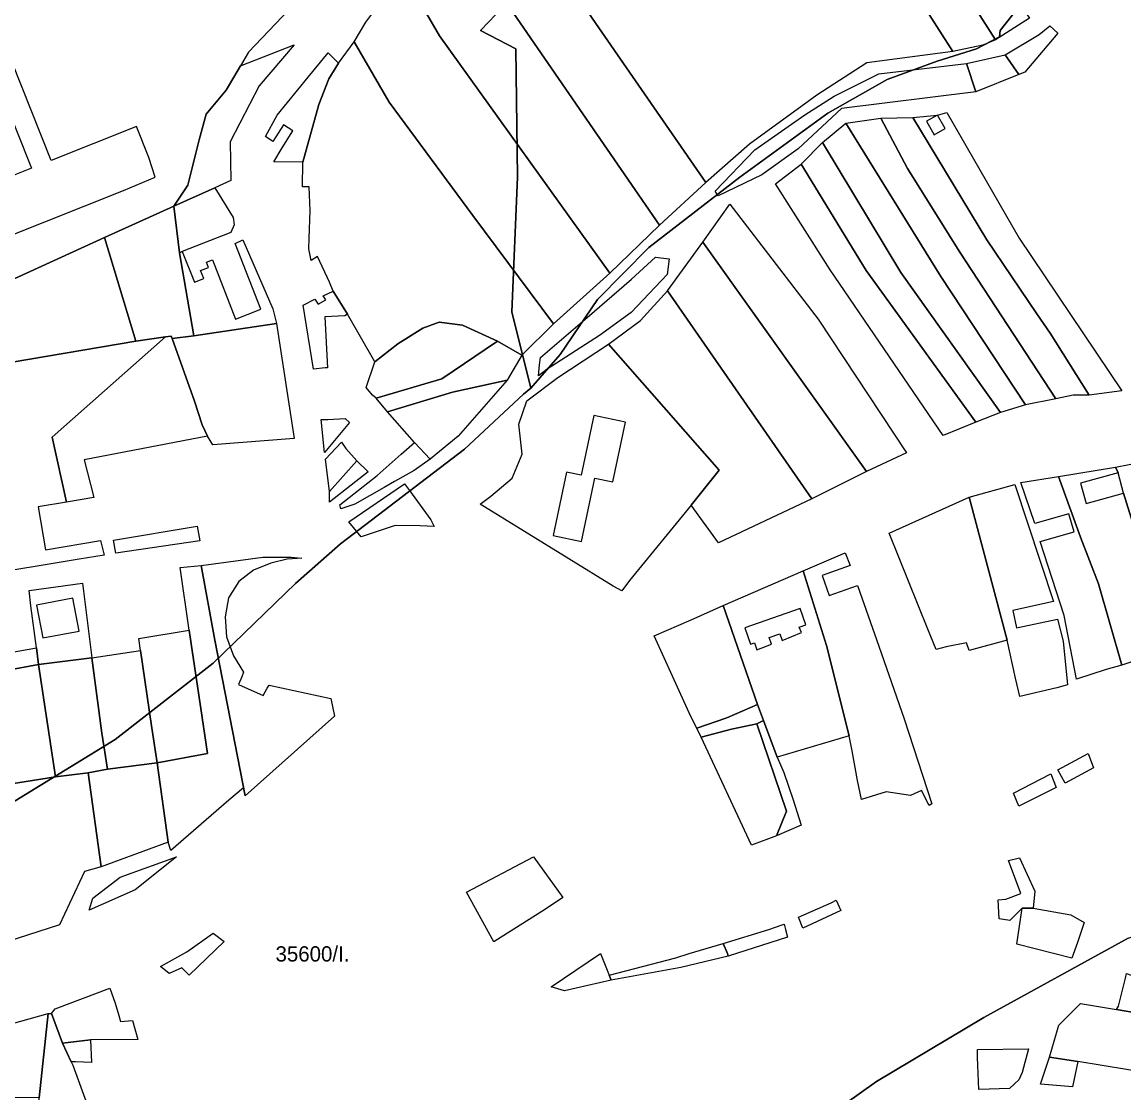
# Model space of a CAD drawing. Extents: x -532083 to -529270, y -1180561 to -1176456.
# Drawn here: x -531139.4 to -530778.9, y -1178347.7 to -1177997.2 of the extents above; entities that cross this region are included whole.
import ezdxf

# ---------------------------------------------------------------- set-up
doc = ezdxf.new("R2010")
doc.units = 0
for name, color, linetype in [('95560013', 7, 'Continuous'), ('95590013', 7, 'Continuous'), ('95610013', 7, 'Continuous'), ('95660013', 7, 'Continuous')]:
    doc.layers.add(name, color=color, linetype=linetype)

msp = doc.modelspace()

# ---------------------------------------------------------------- linework, layer by layer
at = {"layer": '95560013'}
for points in [[(-530820.9913, -1178003.06245), (-530930.6673, -1177831.22145), (-530920.0483, -1177825.55545), (-530869.5383, -1177900.90345), (-530842.0393, -1177949.25845), (-530809.7883, -1177995.91145)], [(-530872.2543, -1177948.23745), (-530914.0103, -1177878.42845), (-530941.5973, -1177837.12545), (-530930.6673, -1177831.22145), (-530820.9913, -1178003.06245), (-530825.0653, -1178004.76545), (-530834.9103, -1178006.80845)], [(-530915.7083, -1178049.71545), (-530951.6933, -1177997.61445), (-530993.4503, -1177936.65945), (-530984.6873, -1177911.73145), (-530959.2033, -1177846.27645), (-530941.5973, -1177837.12545), (-530914.0103, -1177878.42845), (-530872.2543, -1177948.23745), (-530834.9103, -1178006.80845), (-530863.0883, -1178010.55445), (-530879.3833, -1178021.11145), (-530901.4493, -1178037.11645)], [(-530947.0613, -1178079.33945), (-531002.7723, -1178001.74145), (-531014.8703, -1177980.98445), (-531001.4993, -1177960.86645), (-530930.8253, -1178063.69245)], [(-530991.9483, -1178060.49845), (-531019.3263, -1178023.45545), (-531030.7873, -1178003.65745), (-531026.9673, -1177997.27045), (-531014.8703, -1177980.98445), (-531002.7723, -1178001.74145), (-530947.0613, -1178079.33945), (-530965.5253, -1178095.94445)], [(-530800.5353, -1178000.82745), (-530811.3833, -1178013.60045), (-530813.2703, -1178014.31045), (-530817.7503, -1178007.92345), (-530806.6673, -1178001.30045), (-530803.1293, -1177998.46145)], [(-531038.8063, -1178082.35745), (-531042.6983, -1178073.96445), (-531044.8383, -1178075.23345), (-531045.6173, -1178071.42645), (-531045.4223, -1178067.91445), (-531045.1203, -1178058.95245), (-531045.4933, -1178051.07545), (-531047.6113, -1178051.10845), (-531047.5143, -1178043.08645), (-531042.3023, -1178024.23045), (-531039.0233, -1178015.75445), (-531035.8703, -1178010.69345), (-531030.7873, -1178003.65745), (-531019.3263, -1178023.45545), (-530991.9483, -1178060.49845), (-530965.5253, -1178095.94445), (-530975.8543, -1178106.22745), (-530983.8033, -1178101.69345), (-530995.3373, -1178096.37845), (-531002.9743, -1178095.44045), (-531008.2403, -1178097.34545), (-531016.4083, -1178102.46645), (-531023.9643, -1178108.40745), (-531032.8833, -1178092.84045), (-531037.6453, -1178085.27745)], [(-530827.4193, -1178019.98745), (-530871.2943, -1178025.51645), (-530885.4593, -1178038.72045), (-530897.3353, -1178047.18745), (-530911.6433, -1178054.07645), (-530912.6443, -1178052.49845), (-530899.6243, -1178039.00745), (-530883.3133, -1178027.52545), (-530873.7273, -1178021.49845), (-530859.1323, -1178014.17845), (-530830.4853, -1178010.76245)], [(-530813.2703, -1178014.31045), (-530827.4193, -1178019.98745), (-530830.4853, -1178010.76245), (-530817.7503, -1178007.92345)], [(-530838.7863, -1178080.44245), (-530869.8673, -1178030.34345), (-530858.5063, -1178028.62345), (-530849.7183, -1178045.17945), (-530832.5693, -1178072.48645), (-530801.2503, -1178120.46245), (-530811.0813, -1178122.43545)], [(-530832.5693, -1178072.48645), (-530849.7183, -1178045.17945), (-530858.5063, -1178028.62345), (-530847.9393, -1178028.44545), (-530823.7703, -1178068.43845), (-530807.4743, -1178092.74245), (-530803.0933, -1178099.07145), (-530790.2983, -1178119.28945), (-530795.5483, -1178119.27945), (-530801.2503, -1178120.46245)], [(-530790.2983, -1178119.28945), (-530803.0933, -1178099.07145), (-530807.4743, -1178092.74245), (-530823.7703, -1178068.43845), (-530847.9393, -1178028.44545), (-530839.8763, -1178027.64445), (-530843.5293, -1178029.68445), (-530841.0593, -1178034.10845), (-530837.4063, -1178032.06845), (-530839.8763, -1178027.64445), (-530836.8253, -1178026.85245), (-530813.1853, -1178067.90745), (-530779.6063, -1178117.88345)], [(-530851.8613, -1178079.15245), (-530877.5843, -1178036.57945), (-530869.8673, -1178030.34345), (-530838.7863, -1178080.44245), (-530811.0813, -1178122.43545), (-530819.3393, -1178124.99945)], [(-530863.3093, -1178078.50745), (-530884.5303, -1178043.67545), (-530877.5843, -1178036.57945), (-530851.8613, -1178079.15245), (-530819.3393, -1178124.99945), (-530827.4013, -1178128.15445)], [(-530875.0123, -1178078.29245), (-530892.8903, -1178050.12545), (-530884.5303, -1178043.67545), (-530863.3093, -1178078.50745), (-530827.4013, -1178128.15445), (-530838.0183, -1178132.49345)], [(-531090.6953, -1178268.30045), (-531091.5973, -1178265.58545), (-531095.2053, -1178239.64845), (-531078.6683, -1178236.63245), (-531080.4723, -1178224.87045), (-531084.0803, -1178200.74245), (-531084.6823, -1178196.21845), (-531087.6883, -1178175.70945), (-531080.7733, -1178175.10645), (-531076.2633, -1178199.53545), (-531066.3413, -1178250.50545), (-531066.9423, -1178247.79145), (-531071.7193, -1178251.91645)], [(-531116.5533, -1178205.26645), (-531133.9863, -1178207.47245), (-531134.6903, -1178202.00245), (-531136.4593, -1178188.24745), (-531137.0783, -1178183.28645), (-531119.5603, -1178180.83645)], [(-531122.8083, -1178185.77945), (-531134.6053, -1178188.04045), (-531132.5443, -1178198.79045), (-531120.7483, -1178196.52845)], [(-531127.0763, -1178292.72945), (-531147.8233, -1178299.36545), (-531167.3663, -1178304.49245), (-531176.0273, -1178251.70945), (-531165.3103, -1178250.05545), (-531149.8553, -1178247.57545), (-531128.4223, -1178244.26745), (-531117.7563, -1178242.96545), (-531113.5463, -1178273.72945), (-531118.9583, -1178275.23745)], [(-531102.4213, -1178281.26945), (-531117.4553, -1178287.90445), (-531116.2523, -1178283.98345), (-531107.2323, -1178277.04645), (-531088.8913, -1178270.41145)]]:
    msp.add_lwpolyline(points, close=True, dxfattribs=at)
for points in [[(-531155.6903, -1177952.50245), (-531115.2653, -1177942.02045), (-531094.3663, -1177932.91745), (-531032.2163, -1177904.22945), (-530985.0123, -1177891.27045), (-530995.8013, -1177914.67845), (-531001.4993, -1177916.53545), (-531005.8593, -1177924.40945), (-531007.8223, -1177929.87745), (-531013.0553, -1177944.31245), (-531024.3523, -1177963.98845), (-531029.8573, -1177969.73145), (-531065.3143, -1178007.06545), (-531067.9573, -1178011.48345), (-531072.5823, -1178019.43645), (-531079.1893, -1178027.38845), (-531081.3913, -1178035.78345), (-531085.1353, -1178050.58445), (-531089.7823, -1178057.48045), (-531112.3683, -1178067.70445), (-531168.7963, -1178093.47545)], [(-531157.7323, -1178072.85845), (-531106.1623, -1178052.34245), (-531095.8643, -1178047.91845), (-531097.8523, -1178041.56345), (-531101.9153, -1178031.35245), (-531129.8783, -1178042.47745), (-531146.1403, -1178001.60145)], [(-531145.8383, -1178020.91245), (-531136.2503, -1178045.01245), (-531170.2073, -1178058.52145)]]:
    msp.add_lwpolyline(points, dxfattribs=at)
at = {"layer": '95590013'}
for points in [[(-530930.8253, -1178063.69245), (-531001.4993, -1177960.86645), (-530993.4503, -1177936.65945), (-530951.6933, -1177997.61445), (-530915.7083, -1178049.71545)], [(-531047.5143, -1178043.08645), (-531056.9963, -1178042.97245), (-531054.2843, -1178038.40045), (-531050.7533, -1178032.83345), (-531053.9063, -1178030.80945), (-531057.3113, -1178036.24945), (-531059.7083, -1178034.60445), (-531055.9243, -1178027.64645), (-531045.8343, -1178015.24845), (-531039.2753, -1178007.27745), (-531035.8703, -1178010.69345), (-531039.0233, -1178015.75445), (-531042.3023, -1178024.23045)], [(-531071.0823, -1178066.03545), (-531086.9693, -1178072.25745), (-531087.8343, -1178072.75545), (-531089.7823, -1178057.48045), (-531076.3253, -1178051.44145), (-531070.3053, -1178061.21045), (-531069.9503, -1178063.51945)], [(-531102.1233, -1178101.69645), (-531112.3683, -1178067.70445), (-531089.7823, -1178057.48045), (-531087.8343, -1178072.75545), (-531083.2313, -1178099.93045), (-531090.3013, -1178100.74845), (-531090.6173, -1178099.95745), (-531092.5083, -1178100.27345)], [(-531102.1233, -1178101.69645), (-531165.8743, -1178112.42545), (-531168.7963, -1178093.47545), (-531112.3683, -1178067.70445)], [(-531056.1393, -1178095.84445), (-531083.2313, -1178099.93045), (-531087.8343, -1178072.75545), (-531086.9693, -1178072.25745), (-531083.0163, -1178082.34945), (-531079.9603, -1178081.15245), (-531080.9903, -1178078.52145), (-531078.3453, -1178077.48645), (-531079.0253, -1178075.75045), (-531077.1113, -1178075.00045), (-531069.5153, -1178094.39645), (-531061.2443, -1178091.15745), (-531069.6673, -1178069.63745), (-531067.1173, -1178068.49245), (-531057.3783, -1178091.04945)], [(-530940.1613, -1178092.31345), (-530950.4483, -1178099.81745), (-530967.5933, -1178110.76145), (-530970.3983, -1178112.95045), (-530970.0873, -1178109.35445), (-530969.7753, -1178107.00945), (-530954.5003, -1178093.87645), (-530940.0053, -1178081.36945), (-530932.2123, -1178074.17745), (-530927.6923, -1178074.64645), (-530928.3153, -1178079.80545)], [(-531043.9953, -1178110.85545), (-531047.3693, -1178089.85545), (-531043.5983, -1178087.86445), (-531042.5073, -1178089.55645), (-531040.0273, -1178088.16345), (-531040.9203, -1178086.76945), (-531037.6453, -1178085.27745), (-531032.8833, -1178092.84045), (-531033.7483, -1178093.33345), (-531040.2983, -1178093.64245), (-531039.5103, -1178110.36645), (-531040.1843, -1178110.39845)], [(-531050.3733, -1178133.52745), (-531076.9923, -1178135.52445), (-531078.7343, -1178132.77945), (-531080.4753, -1178129.03545), (-531082.9633, -1178121.30045), (-531090.3013, -1178100.74845), (-531083.2313, -1178099.93045), (-531056.1393, -1178095.84445)], [(-531002.1133, -1178113.93845), (-531023.5563, -1178120.28845), (-531024.7813, -1178119.26445), (-531026.8243, -1178116.80545), (-531023.9643, -1178108.40745), (-531016.4083, -1178102.46645), (-531008.2403, -1178097.34545), (-531002.9743, -1178095.44045), (-530995.3373, -1178096.37845), (-530983.8033, -1178101.69345)], [(-531158.7233, -1178152.85845), (-531164.4233, -1178120.19045), (-531165.8743, -1178112.42545), (-531102.1233, -1178101.69645), (-531092.5083, -1178100.27345), (-531129.4843, -1178133.02845), (-531124.8393, -1178154.34945), (-531134.0743, -1178155.90945), (-531131.6993, -1178169.96845), (-531113.7233, -1178166.93245), (-531112.4833, -1178171.69345), (-531120.7303, -1178173.04145), (-531154.2633, -1178178.52145)], [(-531078.7343, -1178132.77945), (-531119.0363, -1178140.51445), (-531115.8583, -1178152.83145), (-531124.8393, -1178154.34945), (-531129.4843, -1178133.02845), (-531092.5083, -1178100.27345), (-531090.6173, -1178099.95745), (-531090.3013, -1178100.74845), (-531082.9633, -1178121.30045), (-531080.4753, -1178129.03545)], [(-530998.5653, -1178118.38445), (-531019.8263, -1178124.77645), (-531023.5563, -1178120.28845), (-531002.1133, -1178113.93845), (-530983.8033, -1178101.69345), (-530975.8543, -1178106.22745), (-530980.6433, -1178114.43745)], [(-531005.8923, -1178140.29645), (-531010.9933, -1178134.81045), (-531019.8263, -1178124.77645), (-530998.5653, -1178118.38445), (-530980.6433, -1178114.43745), (-530996.7223, -1178132.69945)], [(-531032.2443, -1178128.22345), (-531040.4163, -1178138.03445), (-531041.5613, -1178127.31645), (-531039.3913, -1178127.25445), (-531033.7083, -1178126.98745)], [(-531038.7793, -1178150.89845), (-531040.1223, -1178140.29745), (-531034.8383, -1178134.72745), (-531033.4373, -1178136.75845), (-531029.8323, -1178140.85345)], [(-531020.9083, -1178149.49445), (-531030.4763, -1178154.95945), (-531035.1273, -1178156.55945), (-531035.3753, -1178155.21045), (-531023.1673, -1178145.62845), (-531015.3293, -1178138.62745), (-531010.9933, -1178134.81045), (-531005.8923, -1178140.29645), (-531011.1563, -1178143.99045), (-531017.5283, -1178147.58645)], [(-531026.1513, -1178144.43045), (-531038.7793, -1178154.31245), (-531038.7793, -1178150.89845), (-531029.8323, -1178140.85345)], [(-530764.6173, -1178198.14045), (-530779.0463, -1178151.37545), (-530780.8513, -1178144.74845), (-530781.7183, -1178142.91745), (-530768.3323, -1178140.31245), (-530758.7433, -1178140.11245), (-530758.1443, -1178143.11745), (-530753.4013, -1178168.85145), (-530748.2463, -1178196.61945), (-530752.7073, -1178197.22145)], [(-530779.6693, -1178207.74145), (-530787.2383, -1178181.03845), (-530793.0903, -1178165.83145), (-530800.2983, -1178145.92345), (-530781.7183, -1178142.91745), (-530780.8513, -1178144.74845), (-530793.1343, -1178148.09445), (-530791.3293, -1178154.72145), (-530779.0463, -1178151.37545), (-530764.6173, -1178198.14045), (-530763.7573, -1178202.75145), (-530768.3543, -1178203.87745)], [(-530794.4703, -1178212.31645), (-530798.5383, -1178191.37845), (-530806.3273, -1178167.25945), (-530795.2573, -1178164.06545), (-530796.9623, -1178158.15645), (-530808.0323, -1178161.35045), (-530812.6463, -1178147.93445), (-530800.2983, -1178145.92345), (-530793.0903, -1178165.83145), (-530787.2383, -1178181.03845), (-530779.6693, -1178207.74145), (-530784.7253, -1178209.06945)], [(-531009.1943, -1178162.06745), (-531017.2993, -1178161.92645), (-531028.4783, -1178165.71145), (-531032.4693, -1178160.82445), (-531014.2633, -1178148.29445), (-531012.6083, -1178150.46945), (-531005.7013, -1178160.10445), (-531004.5833, -1178162.34745)], [(-530817.1583, -1178199.51445), (-530829.5893, -1178152.66745), (-530814.5763, -1178148.58045), (-530801.9293, -1178186.88145), (-530815.2743, -1178189.77145), (-530814.0403, -1178195.46945), (-530800.6953, -1178192.57945), (-530798.8283, -1178199.81045), (-530797.4313, -1178214.07945), (-530800.8563, -1178215.10645), (-530812.9483, -1178217.98945), (-530814.3693, -1178211.90245)], [(-530843.1133, -1178195.91445), (-530855.7553, -1178164.50045), (-530829.5893, -1178152.66745), (-530817.1583, -1178199.51445), (-530829.5833, -1178202.83845), (-530830.4123, -1178200.34545), (-530837.0393, -1178201.73045), (-530840.3523, -1178202.56145)], [(-531109.4663, -1178166.81645), (-531082.0753, -1178162.18345), (-531081.2653, -1178166.98445), (-531108.7283, -1178170.98745)], [(-531076.2633, -1178199.53545), (-531080.7733, -1178175.10645), (-531060.6593, -1178172.35145), (-531051.3963, -1178172.29945), (-531047.9023, -1178172.72045), (-531052.6543, -1178173.00045), (-531057.9643, -1178174.26245), (-531063.6933, -1178176.64445), (-531068.4443, -1178180.28945), (-531071.7983, -1178185.61545), (-531072.9163, -1178191.92345), (-531072.4973, -1178198.37145), (-531070.2613, -1178204.67945), (-531066.9073, -1178210.00545), (-531067.4663, -1178211.54745), (-531068.5843, -1178214.07045), (-531060.4793, -1178217.57545), (-531059.2213, -1178215.19245), (-531058.5233, -1178214.21145), (-531038.4003, -1178218.55645), (-531037.2013, -1178224.41145), (-531066.3413, -1178250.50545)], [(-530868.8693, -1178230.84145), (-530876.2533, -1178201.21445), (-530883.8513, -1178176.76245), (-530870.1243, -1178170.95345), (-530868.4493, -1178175.03845), (-530877.6803, -1178178.30345), (-530875.3633, -1178184.85145), (-530866.1323, -1178181.58645), (-530859.1293, -1178201.45345), (-530850.8453, -1178225.27345), (-530841.7343, -1178253.12845), (-530842.6253, -1178253.57545), (-530845.1503, -1178248.65945), (-530848.7153, -1178250.29745), (-530856.7063, -1178249.16845), (-530864.7573, -1178251.63845), (-530866.1293, -1178245.49245), (-530867.8743, -1178235.69045)], [(-530868.8693, -1178230.84145), (-530892.3243, -1178237.81245), (-530896.8853, -1178225.83045), (-530898.8403, -1178220.60245), (-530909.9903, -1178188.16745), (-530883.8513, -1178176.76245), (-530876.2533, -1178201.21445)], [(-530898.8403, -1178220.60245), (-530908.8303, -1178224.95945), (-530918.5933, -1178228.32145), (-530920.5753, -1178224.54445), (-530932.6003, -1178198.07945), (-530920.5413, -1178192.87145), (-530909.9903, -1178188.16745)], [(-530898.9933, -1178202.63045), (-530894.1733, -1178200.81745), (-530895.0093, -1178198.68045), (-530891.5233, -1178197.46045), (-530890.7843, -1178199.60845), (-530884.3833, -1178197.04045), (-530885.1363, -1178195.22545), (-530882.9783, -1178194.47045), (-530884.8403, -1178189.14845), (-530902.9503, -1178195.48545), (-530901.0883, -1178200.80745), (-530899.7553, -1178200.34045)], [(-531133.9863, -1178207.47245), (-531155.2133, -1178211.39945), (-531156.0903, -1178205.82545), (-531134.6903, -1178202.00245)], [(-531128.4223, -1178244.26745), (-531133.9863, -1178207.47245), (-531116.5533, -1178205.26645), (-531113.2453, -1178229.99745), (-531111.4413, -1178241.75945), (-531117.7563, -1178242.96545)], [(-531095.2053, -1178239.64845), (-531111.4413, -1178241.75945), (-531113.2453, -1178229.99745), (-531116.5533, -1178205.26645), (-531100.6173, -1178202.85345), (-531097.0093, -1178227.58445)], [(-531128.4223, -1178244.26745), (-531149.8553, -1178247.57545), (-531155.2133, -1178211.39945), (-531133.9863, -1178207.47245)], [(-530899.0573, -1178226.92045), (-530907.3093, -1178228.66245), (-530917.2053, -1178231.30445), (-530918.5933, -1178228.32145), (-530908.8303, -1178224.95945), (-530898.8403, -1178220.60245), (-530896.8853, -1178225.83045)], [(-530892.5413, -1178263.51845), (-530900.7663, -1178266.60245), (-530917.2053, -1178231.30445), (-530907.3093, -1178228.66245), (-530899.0573, -1178226.92045), (-530889.2843, -1178255.45745)], [(-530889.2843, -1178255.45745), (-530899.0573, -1178226.92045), (-530896.8853, -1178225.83045), (-530892.3243, -1178237.81245), (-530890.1523, -1178242.82245), (-530887.1123, -1178251.75445), (-530884.5063, -1178260.03245), (-530892.5413, -1178263.51845)], [(-530788.8453, -1178241.30945), (-530798.1543, -1178246.34845), (-530800.5643, -1178241.96345), (-530790.6673, -1178236.63745)], [(-531091.5973, -1178265.58545), (-531113.5463, -1178273.72945), (-531117.7563, -1178242.96545), (-531111.4413, -1178241.75945), (-531095.2053, -1178239.64845)], [(-530801.1093, -1178247.68245), (-530813.2923, -1178253.80145), (-530815.0483, -1178249.54345), (-530802.8733, -1178243.20645)], [(-530983.8233, -1178297.48645), (-530985.0663, -1178298.19945), (-530993.9473, -1178281.98645), (-530972.0983, -1178270.43345), (-530962.4963, -1178283.72145), (-530968.1613, -1178287.52945)], [(-530812.1923, -1178287.22345), (-530816.3013, -1178291.26145), (-530819.7433, -1178290.70145), (-530820.1163, -1178284.44845), (-530817.6033, -1178284.26145), (-530812.6723, -1178282.39545), (-530816.6623, -1178271.62945), (-530813.1453, -1178270.74545), (-530808.1183, -1178281.64345), (-530808.5763, -1178287.22345)], [(-530871.5383, -1178288.02545), (-530883.9273, -1178293.80145), (-530885.3623, -1178290.21445), (-530874.7093, -1178285.46045), (-530873.0813, -1178284.55645)], [(-530795.9273, -1178303.62245), (-530813.9653, -1178298.97045), (-530812.1923, -1178287.22345), (-530808.5763, -1178287.22345), (-530796.3033, -1178289.42245), (-530791.9963, -1178291.93445), (-530794.1053, -1178298.51145)], [(-531073.2403, -1178298.09645), (-531084.7363, -1178309.13845), (-531087.1623, -1178306.70545), (-531091.2753, -1178308.61045), (-531094.0923, -1178306.30145), (-531085.4663, -1178301.51945), (-531076.8403, -1178295.37145)], [(-530888.9543, -1178296.69945), (-530908.3583, -1178302.91145), (-530908.6343, -1178302.08245), (-530910.0103, -1178298.76945), (-530895.1473, -1178294.21445), (-530890.7443, -1178292.69645), (-530890.0553, -1178292.42045), (-530889.6433, -1178294.21445)], [(-530908.3583, -1178302.91145), (-530923.9093, -1178306.63845), (-530946.6163, -1178310.77945), (-530947.3043, -1178309.12245), (-530925.5613, -1178303.46345), (-530921.1573, -1178302.08245), (-530910.0103, -1178298.76945), (-530908.6343, -1178302.08245)], [(-530946.6163, -1178310.77945), (-530961.8913, -1178314.23045), (-530966.3273, -1178312.94445), (-530950.1593, -1178302.07645), (-530947.3043, -1178309.12245)], [(-530738.9403, -1178328.65345), (-530767.4103, -1178322.75045), (-530781.3253, -1178320.33845), (-530780.7493, -1178319.31045), (-530778.3923, -1178310.10045), (-530778.1133, -1178308.65745), (-530776.5153, -1178309.13745), (-530763.8023, -1178313.10045), (-530750.6853, -1178317.14345)], [(-531101.4973, -1178330.20345), (-531117.0273, -1178330.29745), (-531126.1103, -1178331.40845), (-531129.7223, -1178321.67245), (-531128.5973, -1178320.19045), (-531110.6643, -1178313.35945), (-531108.9183, -1178318.34845), (-531107.6813, -1178322.34545), (-531107.1313, -1178324.27545), (-531103.2833, -1178324.00045)], [(-530770.1593, -1178341.36145), (-530794.0383, -1178337.39745), (-530803.3143, -1178336.01945), (-530800.2223, -1178325.50745), (-530793.1793, -1178318.44245), (-530781.3253, -1178320.33845), (-530767.4103, -1178322.75045)], [(-531133.7863, -1178349.29745), (-531150.2653, -1178349.07045), (-531150.2653, -1178347.25945), (-531150.0393, -1178326.42745), (-531145.9763, -1178325.97445), (-531130.8513, -1178321.67245)], [(-531128.3683, -1178365.37445), (-531134.0113, -1178353.14645), (-531133.7863, -1178349.29745), (-531130.8513, -1178321.67245), (-531129.7223, -1178321.67245), (-531126.1103, -1178331.40845), (-531123.2773, -1178337.47045), (-531122.7243, -1178338.65445), (-531115.0493, -1178359.93945), (-531117.3063, -1178360.84545)], [(-531116.6503, -1178337.72145), (-531121.9193, -1178337.47045), (-531123.2773, -1178337.47045), (-531126.1103, -1178331.40845), (-531117.0273, -1178330.29745)], [(-530816.3743, -1178346.19545), (-530826.4283, -1178346.59445), (-530826.7583, -1178338.76245), (-530826.8093, -1178335.95545), (-530826.8093, -1178333.53345), (-530810.1373, -1178333.30345), (-530812.2043, -1178341.03945), (-530813.3683, -1178343.37445)], [(-530795.7563, -1178345.66945), (-530806.2353, -1178344.80745), (-530803.3143, -1178336.01945), (-530794.0383, -1178337.39745)]]:
    msp.add_lwpolyline(points, close=True, dxfattribs=at)
at = {"layer": '95610013'}
for points in [[(-531076.3253, -1178051.44145), (-531089.7823, -1178057.48045), (-531085.1353, -1178050.58445), (-531081.3913, -1178035.78345), (-531079.1893, -1178027.38845), (-531072.5823, -1178019.43645), (-531067.9573, -1178011.48345), (-531050.3393, -1178004.63545), (-531061.7913, -1178018.11045), (-531071.2613, -1178036.44645), (-531071.0403, -1178049.03745)], [(-530863.1863, -1178144.32745), (-530916.6843, -1178069.26145), (-530907.8953, -1178056.79045), (-530878.9573, -1178094.41845), (-530850.0123, -1178138.21345)], [(-530881.0783, -1178153.20245), (-530928.2593, -1178085.17345), (-530916.6843, -1178069.26145), (-530863.1863, -1178144.32745)], [(-530911.3253, -1178143.87245), (-530947.5513, -1178102.58945), (-530937.0473, -1178094.84845), (-530928.2593, -1178085.17345), (-530881.0783, -1178153.20245), (-530911.5553, -1178167.60045), (-530920.5423, -1178155.26845)], [(-530911.3253, -1178143.87245), (-530920.5423, -1178155.26845), (-530940.6913, -1178179.99445), (-530943.1893, -1178183.38245), (-530946.0173, -1178181.85545), (-530989.5213, -1178155.01745), (-530986.0403, -1178152.39945), (-530979.0803, -1178146.50845), (-530975.8173, -1178138.65345), (-530976.9043, -1178128.83545), (-530974.2943, -1178121.19845), (-530964.0713, -1178113.56245), (-530947.5513, -1178102.58945)], [(-530951.9773, -1178146.48945), (-530946.0783, -1178147.72745), (-530941.9663, -1178128.13745), (-530952.3723, -1178125.95345), (-530956.4843, -1178145.54345), (-530961.2433, -1178144.54445), (-530965.5933, -1178165.27245), (-530956.3283, -1178167.21745)], [(-531078.6683, -1178236.63245), (-531095.2053, -1178239.64845), (-531097.0093, -1178227.58445), (-531100.6173, -1178202.85345), (-531101.2193, -1178198.93245), (-531084.6823, -1178196.21845), (-531084.0803, -1178200.74245), (-531080.4723, -1178224.87045)]]:
    msp.add_lwpolyline(points, close=True, dxfattribs=at)
at = {"layer": '95660013'}
for points in [[(-531146.3753, -1178255.00045), (-531108.8753, -1178232.00045), (-531076.8753, -1178207.00045), (-531049.8753, -1178181.00045), (-531035.1873, -1178168.00045), (-530994.6253, -1178137.00045), (-530975.3753, -1178119.00045), (-530973.0003, -1178117.00045), (-530963.3123, -1178106.00045), (-530951.1873, -1178088.00045), (-530934.3753, -1178071.00045), (-530904.6253, -1178048.00045), (-530875.8123, -1178027.00045), (-530856.3753, -1178016.00045), (-530840.0003, -1178010.00045), (-530827.1253, -1178006.00045), (-530819.6873, -1178002.00045), (-530819.3753, -1178000.00045), (-530803.0003, -1177979.00045), (-530792.6253, -1177959.00045), (-530781.3753, -1177936.00045), (-530775.6253, -1177917.00045)], [(-530961.8753, -1177971.00045), (-530989.3753, -1178000.00045), (-530977.8123, -1178006.00045), (-530977.3123, -1178048.00045), (-530979.1253, -1178092.00045), (-530973.0003, -1178117.00045), (-530975.3753, -1178119.00045), (-530994.6253, -1178137.00045), (-531035.1873, -1178168.00045), (-531049.8753, -1178181.00045), (-531076.8753, -1178207.00045), (-531108.8753, -1178232.00045), (-531146.3753, -1178255.00045)], [(-530803.0003, -1177979.00045), (-530819.3753, -1178000.00045), (-530819.6873, -1178002.00045), (-530827.1253, -1178006.00045), (-530840.0003, -1178010.00045), (-530856.3753, -1178016.00045), (-530875.8123, -1178027.00045), (-530904.6253, -1178048.00045), (-530934.3753, -1178071.00045), (-530951.1873, -1178088.00045), (-530963.3123, -1178106.00045), (-530973.0003, -1178117.00045), (-530979.1253, -1178092.00045), (-530977.3123, -1178048.00045), (-530977.8123, -1178006.00045), (-530989.3753, -1178000.00045), (-530961.8753, -1177971.00045)], [(-530885.1873, -1178362.00045), (-530859.8753, -1178344.00045), (-530824.8123, -1178323.00045), (-530777.5003, -1178297.00045), (-530748.8753, -1178287.00045), (-530713.8123, -1178274.00045), (-530662.3753, -1178261.00045), (-530630.8753, -1178257.00045), (-530597.5003, -1178257.00045), (-530559.8753, -1178255.00045), (-530542.0003, -1178254.00045), (-530537.1253, -1178275.00045), (-530533.8123, -1178299.00045), (-530534.3753, -1178320.00045), (-530534.6873, -1178329.00045), (-530536.6873, -1178345.00045), (-530548.1253, -1178386.00045)], [(-530777.5003, -1178297.00045), (-530824.8123, -1178323.00045), (-530859.8753, -1178344.00045), (-530885.1873, -1178362.00045)]]:
    msp.add_lwpolyline(points, dxfattribs=at)

# ---------------------------------------------------------------- texts
msp.add_text('35600/I.', height=5, rotation=0, dxfattribs=at).set_placement((-531056.4628, -1178304.69234))

doc.saveas('drawing.dxf')
